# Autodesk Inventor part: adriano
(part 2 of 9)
sketch "スケッチ44"
  geometry: L1 (14.5, 50)-(14.5, 46) reference; L2 (0, 50)-(14.5, 50) reference; L3 (14.5, 46)-(0, 46) reference; L4 (1.7, 49.2)-(2.5, 49.2); L5 (2.5, 49.2)-(2.5, 46.8); L6 (2.5, 46.8)-(1.7, 46.8); L7 (1.7, 46.8)-(1.7, 49.2); L8 (3.3, 49.2)-(4.1, 49.2); L9 (4.1, 49.2)-(4.1, 46.8); L10 (4.1, 46.8)-(3.3, 46.8); L11 (3.3, 46.8)-(3.3, 49.2); L12 (6.5, 49.2)-(7.3, 49.2); L13 (7.3, 49.2)-(7.3, 46.8); L14 (7.3, 46.8)-(6.5, 46.8); L15 (6.5, 46.8)-(6.5, 49.2); L16 (8.1, 49.2)-(8.9, 49.2); L17 (8.9, 49.2)-(8.9, 46.8); L18 (8.9, 46.8)-(8.1, 46.8); L19 (8.1, 46.8)-(8.1, 49.2); L20 (9.7, 49.2)-(10.5, 49.2); L21 (10.5, 49.2)-(10.5, 46.8); L22 (10.5, 46.8)-(9.7, 46.8); L23 (9.7, 46.8)-(9.7, 49.2); L24 (11.3, 49.2)-(12.1, 49.2); L25 (12.1, 49.2)-(12.1, 46.8); L26 (12.1, 46.8)-(11.3, 46.8); L27 (11.3, 46.8)-(11.3, 49.2); L28 (12.9, 49.2)-(13.7, 49.2); L29 (13.7, 49.2)-(13.7, 46.8); L30 (13.7, 46.8)-(12.9, 46.8); L31 (12.9, 46.8)-(12.9, 49.2); L32 (4.9, 49.2)-(5.7, 49.2); L33 (5.7, 49.2)-(5.7, 46.8); L34 (5.7, 46.8)-(4.9, 46.8); L35 (4.9, 46.8)-(4.9, 49.2); L36 (0.1, 49.2)-(0.9, 49.2); L37 (0.9, 49.2)-(0.9, 46.8); L38 (0.9, 46.8)-(0.1, 46.8); L39 (0.1, 46.8)-(0.1, 49.2); 1 further point
  constraints: 72 end point, 18 parallel, 9 horizontal, 9 perpendicular
  dimensions: "d480" = 0.8 distance between parallel lines of L1 L29; "d481" = 0.8 distance of L28.start L28.end; "d482" = 0.8 distance between parallel lines of L31 L25; "d483" = 0.8 distance of L24.start L24.end; "d484" = 0.8 distance between parallel lines of L27 L21; "d485" = 0.8 distance of L20.start L20.end; "d486" = 0.8 distance between parallel lines of L23 L17; "d487" = 0.8 distance of L16.start L16.end; "d488" = 0.8 distance between parallel lines of L19 L13; "d489" = 0.8 distance of L12.start L12.end; "d490" = 0.8 distance between parallel lines of L15 L33; "d491" = 0.8 distance of L32.start L32.end; "d492" = 0.8 distance between parallel lines of L35 L9; "d493" = 0.8 distance of L8.start L8.end; "d494" = 0.8 distance between parallel lines of L11 L5; "d495" = 0.8 distance of L4.start L4.end; "d496" = 0.8 distance between parallel lines of L7 L37; "d497" = 0.8 distance of L36.start L36.end; "d498" = 0.8 distance between parallel lines of L2 L28; "d499" = 0.8 distance between parallel lines of L3 L30; "d500" = 0 distance between parallel lines of L30 L26; "d501" = 0 distance between parallel lines of L22 L26; "d502" = 0 distance between parallel lines of L18 L22; "d503" = 0 distance between parallel lines of L14 L18; "d504" = 0 distance between parallel lines of L34 L14; "d505" = 0 distance between parallel lines of L10 L34; "d506" = 0 distance between parallel lines of L10 L6; "d507" = 0 distance between parallel lines of L38 L6
extrude "押し出し43" cut sketch "スケッチ44" distance "d508" = 2; taper "d509" = 0 deg
sketch "スケッチ45"
  geometry: L1 (0, 50)-(43, 50) reference; L2 (0, 46)-(0, 50) reference; L3 (43, 46)-(0, 46) reference; L4 (0.8, 49.2)-(1.6, 49.2); L5 (1.6, 49.2)-(1.6, 46.8); L6 (1.6, 46.8)-(0.8, 46.8); L7 (0.8, 46.8)-(0.8, 49.2); L8 (2.4, 49.2)-(3.2, 49.2); L9 (3.2, 49.2)-(3.2, 46.8); L10 (3.2, 46.8)-(2.4, 46.8); L11 (2.4, 46.8)-(2.4, 49.2); L12 (4, 49.2)-(4.8, 49.2); L13 (4.8, 49.2)-(4.8, 46.8); L14 (4.8, 46.8)-(4, 46.8); L15 (4, 46.8)-(4, 49.2); L16 (5.6, 49.2)-(6.4, 49.2); L17 (6.4, 49.2)-(6.4, 46.8); L18 (6.4, 46.8)-(5.6, 46.8); L19 (5.6, 46.8)-(5.6, 49.2); L20 (7.2, 49.2)-(8, 49.2); L21 (8, 49.2)-(8, 46.8); L22 (8, 46.8)-(7.2, 46.8); L23 (7.2, 46.8)-(7.2, 49.2); L24 (8.8, 49.2)-(9.6, 49.2); L25 (9.6, 49.2)-(9.6, 46.8); L26 (9.6, 46.8)-(8.8, 46.8); L27 (8.8, 46.8)-(8.8, 49.2); L28 (12, 49.2)-(12.8, 49.2); L29 (12.8, 49.2)-(12.8, 46.8); L30 (12.8, 46.8)-(12, 46.8); L31 (12, 46.8)-(12, 49.2); L32 (13.6, 49.2)-(14.4, 49.2); L33 (14.4, 49.2)-(14.4, 46.8); L34 (14.4, 46.8)-(13.6, 46.8); L35 (13.6, 46.8)-(13.6, 49.2); L36 (15.2, 49.2)-(16, 49.2); L37 (16, 49.2)-(16, 46.8); L38 (16, 46.8)-(15.2, 46.8); L39 (15.2, 46.8)-(15.2, 49.2); L40 (16.8, 49.2)-(17.6, 49.2); L41 (17.6, 49.2)-(17.6, 46.8); L42 (17.6, 46.8)-(16.8, 46.8); L43 (16.8, 46.8)-(16.8, 49.2); L44 (18.4, 49.2)-(19.2, 49.2); L45 (19.2, 49.2)-(19.2, 46.8); L46 (19.2, 46.8)-(18.4, 46.8); L47 (18.4, 46.8)-(18.4, 49.2); L48 (20, 49.2)-(20.8, 49.2); L49 (20.8, 49.2)-(20.8, 46.8); L50 (20.8, 46.8)-(20, 46.8); L51 (20, 46.8)-(20, 49.2); L52 (21.6, 49.2)-(22.4, 49.2); L53 (22.4, 49.2)-(22.4, 46.8); L54 (22.4, 46.8)-(21.6, 46.8); L55 (21.6, 46.8)-(21.6, 49.2); L56 (23.2, 49.2)-(24, 49.2); L57 (24, 49.2)-(24, 46.8); L58 (24, 46.8)-(23.2, 46.8); L59 (23.2, 46.8)-(23.2, 49.2); L60 (24.8, 49.2)-(25.6, 49.2); L61 (25.6, 49.2)-(25.6, 46.8); L62 (25.6, 46.8)-(24.8, 46.8); L63 (24.8, 46.8)-(24.8, 49.2); L64 (26.4, 49.2)-(27.2, 49.2)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; 1 further point
  constraints: 216 end point, 54 parallel, 27 horizontal, 27 perpendicular
  dimensions: "d510" = 0.8 distance between parallel lines of L2 L7; "d511" = 0.8 distance of L4.start L4.end; "d512" = 0.8 distance between parallel lines of L11 L5; "d513" = 0.8 distance of L8.start L8.end; "d514" = 0.8 distance between parallel lines of L15 L9; "d515" = 0.8 distance of L12.start L12.end; "d516" = 0.8 distance between parallel lines of L19 L13; "d517" = 0.8 distance of L16.start L16.end; "d518" = 0.8 distance between parallel lines of L23 L17; "d519" = 0.8 distance of L20.start L20.end; "d520" = 0.8 distance between parallel lines of L27 L21; "d521" = 0.8 distance of L24.start L24.end; "d522" = 0.8 distance between parallel lines of L107 L25; "d523" = 0.8 distance of L104.start L104.end; "d524" = 0.8 distance between parallel lines of L31 L105; "d525" = 0.8 distance of L28.start L28.end; "d526" = 0.8 distance between parallel lines of L35 L29; "d527" = 0.8 distance of L32.start L32.end; "d528" = 0.8 distance between parallel lines of L39 L33; "d529" = 0.8 distance of L36.start L36.end; "d530" = 0.8 distance between parallel lines of L43 L37; "d531" = 0.8 distance of L40.start L40.end; "d532" = 0.8 distance between parallel lines of L47 L41; "d533" = 0.8 distance of L44.start L44.end; "d534" = 0.8 distance between parallel lines of L51 L45; "d535" = 0.8 distance of L48.start L48.end; "d536" = 0.8 distance between parallel lines of L55 L49; "d537" = 0.8 distance of L52.start L52.end; "d538" = 0.8 distance between parallel lines of L59 L53; "d539" = 0.8 distance of L56.start L56.end; "d540" = 0.8 distance between parallel lines of L63 L57; "d541" = 0.8 distance of L60.start L60.end; "d542" = 0.8 distance between parallel lines of L67 L61; "d543" = 0.8 distance of L64.start L64.end; "d544" = 0.8 distance between parallel lines of L71 L65; "d545" = 0.8 distance of L68.start L68.end; "d546" = 0.8 distance between parallel lines of L75 L69; "d547" = 0.8 distance of L72.start L72.end; "d548" = 0.8 distance between parallel lines of L79 L73; "d549" = 0.8 distance of L76.start L76.end; "d550" = 0.8 distance between parallel lines of L83 L77; "d551" = 0.8 distance of L80.start L80.end; "d552" = 0.8 distance between parallel lines of L87 L81; "d553" = 0.8 distance of L84.start L84.end; "d554" = 0.8 distance between parallel lines of L85 L91; "d555" = 0.8 distance of L88.start L88.end; "d556" = 0.8 distance between parallel lines of L95 L89; "d557" = 0.8 distance of L92.start L92.end; "d558" = 0.8 distance between parallel lines of L99 L93; "d559" = 0.8 distance of L96.start L96.end; "d560" = 0.8 distance between parallel lines of L103 L97; "d561" = 0.8 distance of L100.start L100.end; "d562" = 0.8 distance between parallel lines of L1 L4; "d563" = 0.8 distance between parallel lines of L3 L6; "d564" = 0 distance between parallel lines of L10 L6; "d565" = 0 distance between parallel lines of L14 L10; "d566" = 0 distance between parallel lines of L18 L14; "d567" = 0 distance between parallel lines of L22 L18; "d568" = 0 distance between parallel lines of L26 L22; "d569" = 0 distance between parallel lines of L106 L26; "d570" = 0 distance between parallel lines of L30 L106; "d571" = 0 distance between parallel lines of L34 L30; "d572" = 0 distance between parallel lines of L38 L34; "d573" = 0 distance between parallel lines of L42 L38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
extrude "押し出し44" cut sketch "スケッチ45" distance "d589" = 2; taper "d590" = 0 deg
sketch "スケッチ46"
  geometry: L1 (-0.5, 4)-(-0.5, 0) reference; L2 (-0.5, 0)-(0, 0) reference; L3 (-0.5, 4)-(0, 4); L4 (0, 4)-(0, 0); L5 (0, 0)-(-0.5, 0); L6 (-0.5, 0)-(-0.5, 4); 1 further point
  constraints: 8 end point, 2 parallel, 1 horizontal, 1 perpendicular
extrude "押し出し45" cut sketch "スケッチ46" distance "d592" = 0.5; taper "d593" = 0 deg
sketch "スケッチ47"
  geometry: L1 (40.8, 49.2)-(41.6, 49.2) reference; L2 (41.6, 49.2)-(41.6, 46.8) reference; L3 (41.6, 46.8)-(40.8, 46.8) reference; L4 (42.4, 49.2)-(43.2, 49.2); L5 (43.2, 49.2)-(43.2, 46.8); L6 (43.2, 46.8)-(42.4, 46.8); L7 (42.4, 46.8)-(42.4, 49.2); 1 further point
  constraints: 8 end point, 2 parallel, 1 horizontal, 1 perpendicular
  dimensions: "d596" = 0.8 distance of L4.start L4.end; "d598" = 0 distance between parallel lines of L3 L6; "d599" = 0 distance between parallel lines of L4 L1; "d600" = 0.8 distance between parallel lines of L7 L2
extrude "押し出し46" cut sketch "スケッチ47" distance "d601" = 0.5; taper "d602" = 0 deg
sketch "スケッチ48"
  geometry: L1 (11.588, -19.314)-(-20.412, -19.314) reference; L2 (11.588, -23.314)-(11.588, -19.314) reference; L3 (55.588, -23.314)-(11.588, -23.314) reference; L4 (11.588, -19.314)-(12.588, -19.314); L5 (12.588, -19.314)-(12.588, -23.314); L6 (12.588, -23.314)-(11.588, -23.314); L7 (11.588, -23.314)-(11.588, -19.314); 1 further point
  constraints: 8 end point, 2 parallel, 2 point on line, 1 horizontal, 1 perpendicular
  dimensions: "d603" = 1 distance of L4.start L4.end; "d605" = 0 distance between parallel lines of L4 L1
extrude "押し出し47" join sketch "スケッチ48" distance "d606" = 4; taper "d607" = 0 deg
sketch "スケッチ49"
  geometry: L1 (0, 50)-(4.5, 50) reference; L2 (0, 46)-(0, 50) reference; L3 (1, 49.2)-(1.8, 49.2); L4 (1.8, 49.2)-(1.8, 46.8); L5 (1.8, 46.8)-(1, 46.8); L6 (1, 46.8)-(1, 49.2); L7 (2.6, 49.2)-(3.4, 49.2); L8 (3.4, 49.2)-(3.4, 46.8); L9 (3.4, 46.8)-(2.6, 46.8); L10 (2.6, 46.8)-(2.6, 49.2); L11 (5.9, 46.8)-(5.1, 46.8) reference; 1 further point
  constraints: 16 end point, 4 parallel, 2 horizontal, 2 perpendicular
  dimensions: "d608" = 1 distance between parallel lines of L2 L6; "d609" = 0.8 distance between parallel lines of L10 L4; "d610" = 0.8 distance of L3.start L3.end; "d611" = 0.8 distance of L7.start L7.end; "d612" = 0.8 distance between parallel lines of L7 L1; "d613" = 0 distance from line of L7 L3.start; "d614" = 0 distance between parallel lines of L11 L9; "d615" = 0 distance between parallel lines of L5 L9
extrude "押し出し48" cut sketch "スケッチ49" distance "d616" = 2; taper "d617" = 0 deg
sketch "スケッチ50"
  geometry: L1 (0, 0)-(0, 26) reference; L2 (31.8, 0)-(0, 0) reference; L3 (4, 8)-(4, 0); L4 (9, 0)-(9, 8); L5 (15, 8)-(15, 2); L6 (15, 2)-(20, 2); L7 (20, 2)-(20, 8); A1 r 2.5 centre (6.5, 8) between (9, 8) and (4, 8); A2 r 2.5 centre (17.5, 8) between (20, 8) and (15, 8); 1 further point
  constraints: 10 end point, 4 point on circle, 4 tangent, 3 parallel, 2 centre point, 2 perpendicular, 2 point on line
  dimensions: "d618" = 6 distance between parallel lines of L5 L4; "d620" = 5 distance between parallel lines of L4 L3; "d621" = 5 distance of L5.end L6.end; "d622" = 4 distance between parallel lines of L1 L3; "d623" = 8 distance from line of L2 A1.centre; "d624" = 0 vertical distance of A1.centre A2.centre; "d625" = 2 distance between parallel lines of L2 L6
extrude "押し出し49" cut sketch "スケッチ50" distance "d626" = 8; taper "d627" = 0 deg
sketch "スケッチ51"
  geometry: L1 (9, -18)-(9, -26) reference; L2 (31.8, -26)-(9, -26) reference; L3 (4, -26)-(4, -18) reference; L4 (15, -18)-(15, -24); L5 (15, -24)-(20, -24); L6 (20, -24)-(20, -18); A1 r 2.5 centre (6.5, -18) between (9, -18) and (4, -18) reference; A2 r 2.5 centre (17.5, -18) between (20, -18) and (15, -18); 1 further point
  constraints: 6 end point, 2 parallel, 2 point on circle, 2 tangent, 1 centre point, 1 perpendicular
  dimensions: "d628" = 6 distance between parallel lines of L4 L1; "d629" = 5 distance of L4.end L5.end; "d630" = 2 distance between parallel lines of L2 L5; "d631" = 0 vertical distance of A1.centre A2.centre
extrude "押し出し50" cut sketch "スケッチ51" distance "d632" = 0.5; taper "d633" = 0 deg
sketch "スケッチ52"
  geometry: L1 (15, -24)-(15, -18) reference; L2 (20, -24)-(15, -24) reference; L3 (20, -18)-(20, -24) reference; L4 (15.6, -21.2)-(17.25, -21.2); L5 (17.25, -21.2)-(17.25, -23.4); L6 (17.25, -23.4)-(15.6, -23.4); L7 (15.6, -23.4)-(15.6, -21.2); L8 (17.75, -21.2)-(19.4, -21.2); L9 (19.4, -21.2)-(19.4, -23.4); L10 (19.4, -23.4)-(17.75, -23.4); L11 (17.75, -23.4)-(17.75, -21.2); L12 (15.6, -18.6)-(17.25, -18.6); L13 (17.25, -18.6)-(17.25, -20.6); L14 (17.25, -20.6)-(15.6, -20.6); L15 (15.6, -20.6)-(15.6, -18.6); L16 (17.75, -18.6)-(19.4, -18.6); L17 (19.4, -18.6)-(19.4, -20.6); L18 (19.4, -20.6)-(17.75, -20.6); L19 (17.75, -20.6)-(17.75, -18.6); L20 (15.6, -18)-(17.25, -18); L21 (17.25, -18)-(17.25, -16.35); L22 (17.75, -16.35)-(17.75, -18); L23 (17.75, -18)-(19.4, -18); A1 r 2.5 centre (17.5, -18) between (20, -18) and (15, -18) reference; A2 r 1.65 centre (17.25, -18) between (17.25, -16.35) and (15.6, -18); A3 r 1.65 centre (17.75, -18) between (19.4, -18) and (17.75, -16.35); 1 further point
  constraints: 40 end point, 9 parallel, 7 perpendicular, 4 horizontal, 4 point on circle, 2 centre point
  dimensions: "d634" = 0.25 distance from line of A1.centre L21; "d635" = 0.5 distance between parallel lines of L22 L21; "d636" = 0.5 distance between parallel lines of L19 L13; "d637" = 0.5 distance between parallel lines of L11 L5; "d638" = 0.25 distance from line of L13 A1.centre; "d639" = 0 distance between parallel lines of L5 L13; "d640" = 0.6 distance between parallel lines of L12 L20; "d641" = 0 distance between parallel lines of L16 L12; "d642" = 0 distance between parallel lines of L18 L14; "d643" = 0.6 distance between parallel lines of L14 L4; "d644" = 0 distance between parallel lines of L8 L4; "d645" = 0 distance between parallel lines of L10 L6; "d646" = 0.6 distance between parallel lines of L2 L6; "d647" = 0 distance between parallel lines of L20 L23; "d648" = 0 distance from line of A1.centre L23; "d649" = 0.6 distance between parallel lines of L15 L1; "d650" = 0.6 distance between parallel lines of L3 L17; "d651" = 0 distance between parallel lines of L7 L15; "d652" = 0 distance between parallel lines of L17 L9; "d653" = 0 horizontal distance of L12.start L20.start; "d654" = 0 vertical distance of L22.start L21.end; "d655" = 2 distance of L16.end L17.end
extrude "押し出し51" cut sketch "スケッチ52" distance "d656" = 4; taper "d657" = 0 deg
sketch "スケッチ53"
  geometry: L1 (-18.412, -5.686)-(13.588, -5.686); L2 (13.588, -5.686)-(13.588, -9.686); L3 (13.588, -9.686)-(-18.412, -9.686); L4 (-18.412, -9.686)-(-18.412, -5.686); 1 further point
  constraints: 8 end point, 2 parallel, 1 horizontal, 1 perpendicular
  dimensions: "d658" = 4 distance of L1.end L2.end; "d660" = 32 distance of L1.start L1.end
extrude "押し出し52" cut sketch "スケッチ53" distance "d661" = 36; taper "d662" = 0 deg
sketch "スケッチ54"
  geometry: L1 (-25.373, 26)-(-25.373, 30) reference; L2 (0, 26)-(-25.373, 26) reference; L3 (-25.373, 30)-(0, 30) reference; L4 (-24.573, 29.2)-(-23.773, 29.2); L5 (-23.773, 29.2)-(-23.773, 26.8); L6 (-23.773, 26.8)-(-24.573, 26.8); L7 (-24.573, 26.8)-(-24.573, 29.2); L8 (-22.973, 29.2)-(-22.173, 29.2); L9 (-22.173, 29.2)-(-22.173, 26.8); L10 (-22.173, 26.8)-(-22.973, 26.8); L11 (-22.973, 26.8)-(-22.973, 29.2); L12 (-21.373, 29.2)-(-20.573, 29.2); L13 (-20.573, 29.2)-(-20.573, 26.8); L14 (-20.573, 26.8)-(-21.373, 26.8); L15 (-21.373, 26.8)-(-21.373, 29.2); L16 (-19.773, 29.2)-(-18.973, 29.2); L17 (-18.973, 29.2)-(-18.973, 26.8); L18 (-18.973, 26.8)-(-19.773, 26.8); L19 (-19.773, 26.8)-(-19.773, 29.2); L20 (-18.173, 29.2)-(-17.373, 29.2); L21 (-17.373, 29.2)-(-17.373, 26.8); L22 (-17.373, 26.8)-(-18.173, 26.8); L23 (-18.173, 26.8)-(-18.173, 29.2); L24 (-16.573, 29.2)-(-15.773, 29.2); L25 (-15.773, 29.2)-(-15.773, 26.8); L26 (-15.773, 26.8)-(-16.573, 26.8); L27 (-16.573, 26.8)-(-16.573, 29.2); L28 (-13.373, 29.2)-(-12.573, 29.2); L29 (-12.573, 29.2)-(-12.573, 26.8); L30 (-12.573, 26.8)-(-13.373, 26.8); L31 (-13.373, 26.8)-(-13.373, 29.2); L32 (-11.773, 29.2)-(-10.973, 29.2); L33 (-10.973, 29.2)-(-10.973, 26.8); L34 (-10.973, 26.8)-(-11.773, 26.8); L35 (-11.773, 26.8)-(-11.773, 29.2); L36 (-10.173, 29.2)-(-9.373, 29.2); L37 (-9.373, 29.2)-(-9.373, 26.8); L38 (-9.373, 26.8)-(-10.173, 26.8); L39 (-10.173, 26.8)-(-10.173, 29.2); L40 (-8.573, 29.2)-(-7.773, 29.2); L41 (-7.773, 29.2)-(-7.773, 26.8); L42 (-7.773, 26.8)-(-8.573, 26.8); L43 (-8.573, 26.8)-(-8.573, 29.2); L44 (-6.973, 29.2)-(-6.173, 29.2); L45 (-6.173, 29.2)-(-6.173, 26.8); L46 (-6.173, 26.8)-(-6.973, 26.8); L47 (-6.973, 26.8)-(-6.973, 29.2); L48 (-5.373, 29.2)-(-4.573, 29.2); L49 (-4.573, 29.2)-(-4.573, 26.8); L50 (-4.573, 26.8)-(-5.373, 26.8); L51 (-5.373, 26.8)-(-5.373, 29.2); L52 (-2.173, 29.2)-(-1.373, 29.2); L53 (-1.373, 29.2)-(-1.373, 26.8); L54 (-1.373, 26.8)-(-2.173, 26.8); L55 (-2.173, 26.8)-(-2.173, 29.2); L56 (-14.973, 29.2)-(-14.173, 29.2); L57 (-14.173, 29.2)-(-14.173, 26.8); L58 (-14.173, 26.8)-(-14.973, 26.8); L59 (-14.973, 26.8)-(-14.973, 29.2); L60 (-3.773, 29.2)-(-2.973, 29.2); L61 (-2.973, 29.2)-(-2.973, 26.8); L62 (-2.973, 26.8)-(-3.773, 26.8); L63 (-3.773, 26.8)-(-3.773, 29.2); 1 further point
  constraints: 120 end point, 30 parallel, 15 horizontal, 15 perpendicular
  dimensions: "d663" = 0.8 distance between parallel lines of L1 L7; "d664" = 0.8 distance of L4.start L4.end; "d665" = 0.8 distance between parallel lines of L11 L5; "d666" = 0.8 distance of L8.start L8.end; "d667" = 0.8 distance between parallel lines of L15 L9; "d668" = 0.8 distance of L12.start L12.end; "d669" = 0.8 distance between parallel lines of L19 L13; "d670" = 0.8 distance of L16.start L16.end; "d671" = 0.8 distance between parallel lines of L23 L17; "d672" = 0.8 distance of L20.start L20.end; "d673" = 0.8 distance between parallel lines of L27 L21; "d674" = 0.8 distance of L24.start L24.end; "d675" = 0.8 distance between parallel lines of L59 L25; "d676" = 0.8 distance of L56.start L56.end; "d677" = 0.8 distance between parallel lines of L31 L57; "d678" = 0.8 distance of L28.start L28.end; "d679" = 0.8 distance between parallel lines of L35 L29; "d680" = 0.8 distance of L32.start L32.end; "d681" = 0.8 distance between parallel lines of L39 L33; "d682" = 0.8 distance of L36.start L36.end; "d683" = 0.8 distance between parallel lines of L43 L37; "d684" = 0.8 distance of L40.start L40.end; "d685" = 0.8 distance between parallel lines of L47 L41; "d686" = 0.8 distance of L44.start L44.end; "d687" = 0.8 distance between parallel lines of L51 L45; "d688" = 0.8 distance of L48.start L48.end; "d689" = 0.8 distance between parallel lines of L63 L49; "d690" = 0.8 distance of L60.start L60.end; "d691" = 0.8 distance between parallel lines of L55 L61; "d692" = 0.8 distance of L52.start L52.end; "d693" = 0.8 distance between parallel lines of L3 L4; "d694" = 0.8 distance between parallel lines of L2 L6; "d695" = 0 distance between parallel lines of L10 L6; "d696" = 0 distance between parallel lines of L14 L10; "d697" = 0 distance between parallel lines of L18 L14; "d698" = 0 distance between parallel lines of L22 L18; "d699" = 0 distance between parallel lines of L26 L22; "d700" = 0 distance between parallel lines of L58 L26; "d701" = 0 distance between parallel lines of L30 L58; "d702" = 0 distance between parallel lines of L34 L30; "d703" = 0 distance between parallel lines of L38 L34; "d704" = 0 distance between parallel lines of L42 L38; "d705" = 0 distance between parallel lines of L46 L42; "d706" = 0 distance between parallel lines of L50 L46; "d707" = 0 distance between parallel lines of L62 L50; "d708" = 0 distance between parallel lines of L54 L62
extrude "押し出し53" cut sketch "スケッチ54" distance "d709" = 2; taper "d710" = 0 deg
sketch "スケッチ55"
  geometry: L1 (-20.412, 10.686)-(12.588, 10.686); L2 (12.588, 10.686)-(12.588, -19.314); L3 (12.588, -19.314)-(-20.412, -19.314); L4 (-20.412, -19.314)-(-20.412, 10.686); 1 further point
  constraints: 8 end point, 2 parallel, 1 horizontal, 1 perpendicular
extrude "押し出し54" cut sketch "スケッチ55" distance "d711" = 2; taper "d712" = 0 deg
sketch "スケッチ56"
  geometry: L1 (12.588, 10.686)-(12.588, -19.314) reference; L2 (-20.412, 10.686)-(11.388, 10.686) reference; L3 (-20.412, -19.314)-(-20.412, 10.686) reference; L4 (11.588, -19.314)-(-20.412, -19.314) reference; L5 (-19.412, 9.686)-(12.588, 9.686); L6 (12.588, 9.686)-(12.588, -18.314); L7 (12.588, -18.314)-(-19.412, -18.314); L8 (-19.412, -18.314)-(-19.412, 9.686); 1 further point
  constraints: 8 end point, 2 parallel, 1 horizontal, 1 perpendicular, 1 point on line
  dimensions: "d713" = 1 distance between parallel lines of L2 L5; "d714" = 1 distance between parallel lines of L8 L3; "d715" = 1 distance between parallel lines of L4 L7
extrude "押し出し55" cut sketch "スケッチ56" distance "d716" = 4; taper "d717" = 0 deg
sketch "スケッチ57"
  geometry: L1 (-20.412, 10.686)-(11.388, 10.686) reference; L2 (12.588, 9.686)-(0.588, 9.686); L3 (0.588, 9.686)-(0.588, 10.686); L4 (0.588, 10.686)-(12.588, 10.686); L5 (12.588, 10.686)-(12.588, 9.686); 1 further point
  constraints: 8 end point, 2 parallel, 1 horizontal, 1 perpendicular, 1 point on line
  dimensions: "d718" = 12 distance of L3.end L4.end
extrude "押し出し56" join sketch "スケッチ57" distance "d720" = 2; taper "d721" = 0 deg
fillet "フィレット1" dims "d723" = 2
fillet "フィレット2" dims "d724" = 2
sketch "スケッチ58"
  geometry: L1 (12.588, 9.686)-(12.588, -18.314) reference; L2 (-19.412, 9.686)-(12.588, 9.686) reference; L3 (12.588, -18.314)-(-19.412, -18.314) reference; L4 (6.588, -2.314)-(12.588, -2.314); L5 (12.588, -2.314)-(12.588, -8.314); L6 (12.588, -8.314)-(6.588, -8.314); L7 (6.588, -8.314)-(6.588, -2.314); 1 further point
  constraints: 8 end point, 2 parallel, 1 horizontal, 1 perpendicular, 1 point on line
  dimensions: "d725" = 6 distance of L4.start L4.end; "d727" = 12 distance between parallel lines of L2 L4; "d728" = 10 distance between parallel lines of L3 L6
extrude "押し出し57" join sketch "スケッチ58" distance "d729" = 1; taper "d730" = 0 deg
sketch "スケッチ59"
  geometry: L1 (12.588, -2.314)-(12.588, -8.314) reference; L2 (12.588, -2.314)-(6.588, -2.314) reference; L3 (6.588, -2.314)-(6.588, -8.314) reference; L4 (12.588, -8.314)-(7.588, -8.314); L5 (7.588, -8.314)-(7.588, -2.314); L6 (7.588, -2.314)-(12.588, -2.314); L7 (12.588, -2.314)-(12.588, -8.314); 1 further point
  constraints: 8 end point, 2 parallel, 1 horizontal, 1 perpendicular, 1 point on line
  dimensions: "d731" = 1 distance between parallel lines of L5 L3
extrude "押し出し58" join sketch "スケッチ59" distance "d732" = 1; taper "d733" = 0 deg
sketch "スケッチ60"
  geometry: L1 (12.588, -2.314)-(12.588, -8.314) reference; L2 (12.588, -2.314)-(7.588, -2.314) reference; L3 (7.588, -2.314)-(7.588, -8.314) reference; L4 (12.588, -8.314)-(8.588, -8.314); L5 (8.588, -8.314)-(8.588, -2.314); L6 (8.588, -2.314)-(12.588, -2.314); L7 (12.588, -2.314)-(12.588, -8.314); 1 further point
  constraints: 8 end point, 2 parallel, 1 horizontal, 1 perpendicular, 1 point on line
  dimensions: "d734" = 1 distance between parallel lines of L5 L3
extrude "押し出し59" join sketch "スケッチ60" distance "d735" = 1; taper "d736" = 0 deg
sketch "スケッチ61"
  geometry: L1 (12.588, -2.314)-(12.588, -8.314) reference; L2 (12.588, -2.314)-(8.588, -2.314) reference; L3 (8.588, -2.314)-(8.588, -8.314) reference; L4 (12.588, -8.314)-(9.588, -8.314); L5 (9.588, -8.314)-(9.588, -2.314); L6 (9.588, -2.314)-(12.588, -2.314); L7 (12.588, -2.314)-(12.588, -8.314); 1 further point
  constraints: 8 end point, 2 parallel, 1 horizontal, 1 perpendicular, 1 point on line
  dimensions: "d737" = 1 distance between parallel lines of L5 L3
extrude "押し出し60" join sketch "スケッチ61" distance "d738" = 1; taper "d739" = 0 deg
sketch "スケッチ62"
  geometry: L1 (12.588, -2.314)-(12.588, -8.314) reference; L2 (12.588, -2.314)-(9.588, -2.314) reference; L3 (9.588, -2.314)-(9.588, -8.314) reference; L4 (12.588, -8.314)-(10.588, -8.314); L5 (10.588, -8.314)-(10.588, -2.314); L6 (10.588, -2.314)-(12.588, -2.314); L7 (12.588, -2.314)-(12.588, -8.314); 1 further point
  constraints: 8 end point, 2 parallel, 1 horizontal, 1 perpendicular, 1 point on line
  dimensions: "d740" = 1 distance between parallel lines of L3 L5
extrude "押し出し61" join sketch "スケッチ62" distance "d741" = 1; taper "d742" = 0 deg
sketch "スケッチ63"
  geometry: L1 (0, 0)-(0, 5) reference; L2 (0, 0)-(0, 4); L3 (0, 4)-(5, 0); L4 (5, 0)-(0, 0); 1 further point
  constraints: 6 end point, 1 collinear, 1 perpendicular
  dimensions: "d743" = 4 distance of L1.start L2.end; "d744" = 5 distance of L3.end L1.start
extrude "押し出し62" join sketch "スケッチ63" distance "d745" = 12; taper "d746" = 0 deg
sketch "スケッチ64"
  geometry: L1 (6, 5)-(6, 0) reference; L2 (0, 0)-(0, 1) reference; L3 (6, 0)-(1, 0); L4 (1, 0)-(6, 4); L5 (6, 4)-(6, 0); 1 further point
  constraints: 6 end point, 1 collinear, 1 perpendicular
  dimensions: "d747" = 4 distance of L4.end L1.end; "d748" = 5 distance of L1.end L3.end
extrude "押し出し63" join sketch "スケッチ64" distance "d749" = 10; taper "d750" = 0 deg
sketch "スケッチ65"
  geometry: L1 (54.588, 40.686)-(54.588, 32.686) reference; L2 (87.588, 32.686)-(54.588, 32.686) reference; L3 (87.588, 32.686)-(87.588, 40.686) reference; L4 (87.588, 40.686)-(54.588, 40.686) reference; L5 (55.588, 40.686)-(86.588, 40.686); L6 (86.588, 40.686)-(86.588, 32.686); L7 (86.588, 32.686)-(55.588, 32.686); L8 (55.588, 32.686)-(55.588, 40.686); 1 further point
  constraints: 8 end point, 2 parallel, 2 point on line, 1 horizontal, 1 perpendicular
  dimensions: "d751" = 1 distance between parallel lines of L8 L1; "d752" = 1 distance between parallel lines of L3 L6
extrude "押し出し64" join sketch "スケッチ65" distance "d753" = 1; taper "d754" = 0 deg
sketch "スケッチ66"
  geometry: L1 (-17, 18)-(-17, 17) reference; L2 (-48, 17)-(-48, 18) reference; L3 (-48, 18)-(-17, 18) reference; L4 (-25, 18)-(-40, 18); L5 (-40, 18)-(-40, 31); L6 (-40, 31)-(-25, 31); L7 (-25, 31)-(-25, 18); L8 (-75.5, 30)-(13.717, 30) reference; 1 further point
  constraints: 8 end point, 2 parallel, 1 horizontal, 1 perpendicular, 1 point on line
  dimensions: "d755" = 8 distance between parallel lines of L5 L2; "d756" = 8 distance between parallel lines of L7 L1; "d757" = 1 distance between parallel lines of L8 L6
extrude "押し出し65" cut sketch "スケッチ66" distance "d758" = 12; taper "d759" = 0 deg
sketch "スケッチ67"
  geometry: L1 (63.588, 32.686)-(78.588, 32.686); L2 (78.588, 32.686)-(78.588, 20.686); L3 (78.588, 20.686)-(63.588, 20.686); L4 (63.588, 20.686)-(63.588, 32.686); 1 further point
  constraints: 8 end point, 2 parallel, 1 horizontal, 1 perpendicular
extrude "step_00" join sketch "スケッチ67" distance "d760" = 1; taper "d761" = 0 deg
sketch "スケッチ68"
  geometry: L1 (63.588, 20.686)-(63.588, 32.686) reference; L2 (78.588, 32.686)-(63.588, 32.686) reference; L3 (78.588, 20.686)-(63.588, 20.686); L4 (63.588, 20.686)-(63.588, 31.686); L5 (63.588, 31.686)-(78.588, 31.686); L6 (78.588, 31.686)-(78.588, 20.686); 1 further point
  constraints: 8 end point, 2 parallel, 1 horizontal, 1 perpendicular, 1 point on line
  dimensions: "d762" = 1 distance between parallel lines of L5 L2
extrude "押し出し67" join sketch "スケッチ68" distance "d763" = 1; taper "d764" = 0 deg
sketch "スケッチ69"
  geometry: L1 (63.588, 20.686)-(63.588, 31.686) reference; L2 (78.588, 20.686)-(63.588, 20.686) reference; L3 (78.588, 31.686)-(78.588, 20.686) reference; L4 (78.588, 31.686)-(63.588, 31.686) reference; 1 further point
sketch "スケッチ70"
  geometry: L1 (63.588, 20.686)-(63.588, 31.686) reference; L2 (78.588, 31.686)-(63.588, 31.686) reference; L3 (78.588, 20.686)-(63.588, 20.686); L4 (63.588, 20.686)-(63.588, 30.686); L5 (63.588, 30.686)-(78.588, 30.686); L6 (78.588, 30.686)-(78.588, 20.686); 1 further point
  constraints: 8 end point, 2 parallel, 1 horizontal, 1 perpendicular, 1 point on line
  dimensions: "d765" = 1 distance between parallel lines of L5 L2
extrude "押し出し68" join sketch "スケッチ70" distance "d766" = 1; taper "d767" = 0 deg
sketch "スケッチ71"
  geometry: L1 (63.588, 20.686)-(63.588, 30.686) reference; L2 (78.588, 30.686)-(63.588, 30.686) reference; L3 (78.588, 20.686)-(63.588, 20.686); L4 (63.588, 20.686)-(63.588, 29.686); L5 (63.588, 29.686)-(78.588, 29.686); L6 (78.588, 29.686)-(78.588, 20.686); 1 further point
  constraints: 8 end point, 2 parallel, 1 horizontal, 1 perpendicular, 1 point on line
  dimensions: "d768" = 1 distance between parallel lines of L2 L5
extrude "押し出し69" join sketch "スケッチ71" distance "d769" = 1; taper "d770" = 0 deg
sketch "スケッチ72"
  geometry: L1 (78.588, 29.686)-(78.588, 20.686) reference; L2 (78.588, 29.686)-(63.588, 29.686) reference; L3 (63.588, 20.686)-(78.588, 20.686); L4 (78.588, 20.686)-(78.588, 28.686); L5 (78.588, 28.686)-(63.588, 28.686); L6 (63.588, 28.686)-(63.588, 20.686); 1 further point
  constraints: 8 end point, 2 parallel, 1 horizontal, 1 perpendicular, 1 point on line
  dimensions: "d771" = 1 distance between parallel lines of L5 L2
extrude "押し出し70" join sketch "スケッチ72" distance "d772" = 1; taper "d773" = 0 deg
sketch "スケッチ73"
  geometry: L1 (78.588, 20.686)-(63.588, 20.686) reference; L2 (78.588, 28.686)-(78.588, 20.686) reference; L3 (78.588, 28.686)-(63.588, 28.686) reference; L4 (63.588, 20.686)-(78.588, 20.686); L5 (78.588, 20.686)-(78.588, 27.686); L6 (78.588, 27.686)-(63.588, 27.686); L7 (63.588, 27.686)-(63.588, 20.686); 1 further point
  constraints: 8 end point, 2 parallel, 1 horizontal, 1 perpendicular, 1 point on line
  dimensions: "d774" = 1 distance between parallel lines of L3 L6
extrude "押し出し71" join sketch "スケッチ73" distance "d775" = 1; taper "d776" = 0 deg
sketch "スケッチ74"
  geometry: L1 (78.588, 20.686)-(63.588, 20.686) reference; L2 (78.588, 27.686)-(78.588, 20.686) reference; L3 (78.588, 27.686)-(63.588, 27.686) reference; L4 (63.588, 20.686)-(78.588, 20.686); L5 (78.588, 20.686)-(78.588, 26.686); L6 (78.588, 26.686)-(63.588, 26.686); L7 (63.588, 26.686)-(63.588, 20.686); 1 further point
  constraints: 8 end point, 2 parallel, 1 horizontal, 1 perpendicular, 1 point on line
  dimensions: "d777" = 1 distance between parallel lines of L3 L6
extrude "押し出し72" join sketch "スケッチ74" distance "d778" = 1; taper "d779" = 0 deg
sketch "スケッチ75"
  geometry: L1 (78.588, 20.686)-(63.588, 20.686) reference; L2 (78.588, 26.686)-(78.588, 20.686) reference; L3 (78.588, 26.686)-(63.588, 26.686) reference; L4 (63.588, 20.686)-(78.588, 20.686); L5 (78.588, 20.686)-(78.588, 25.686); L6 (78.588, 25.686)-(63.588, 25.686); L7 (63.588, 25.686)-(63.588, 20.686); 1 further point
  constraints: 8 end point, 2 parallel, 1 horizontal, 1 perpendicular, 1 point on line
  dimensions: "d780" = 1 distance between parallel lines of L6 L3
extrude "step_end" join sketch "スケッチ75" distance "d781" = 1; taper "d782" = 0 deg
sketch "スケッチ76"
  geometry: L1 (-54, 26)-(-89.5, 26) reference; L2 (-54, 30)-(-58, 30); L3 (-58, 30)-(-58, 26); L4 (-58, 26)-(-54, 26); L5 (-54, 26)-(-54, 30); L6 (-62, 17)-(-62, 18) reference; 1 further point
  constraints: 8 end point, 2 parallel, 1 horizontal, 1 perpendicular, 1 point on line
  dimensions: "d783" = 4 distance between parallel lines of L6 L3
extrude "押し出し74" cut sketch "スケッチ76" distance "d784" = 2; taper "d785" = 0 deg
sketch "スケッチ77"
  geometry: L1 (-39, 30)-(-39, 26) reference; L2 (-0.283, 26)-(-39, 26) reference; L3 (-39, 30)-(-35, 30); L4 (-35, 30)-(-35, 26); L5 (-35, 26)-(-39, 26); L6 (-39, 26)-(-39, 30); L7 (-31, 17)-(-31, 18) reference; 1 further point
  constraints: 8 end point, 2 parallel, 1 horizontal, 1 perpendicular, 1 point on line
  dimensions: "d786" = 4 distance between parallel lines of L7 L4
extrude "押し出し75" cut sketch "スケッチ77" distance "d787" = 2; taper "d788" = 0 deg
sketch "スケッチ78"
  geometry: L1 (-89.5, 30)-(-58, 30) reference; L2 (-89.5, 26)-(-89.5, 30) reference; L3 (-58, 26)-(-89.5, 26) reference; L4 (-88.7, 29.2)-(-87.9, 29.2); L5 (-87.9, 29.2)-(-87.9, 26.8); L6 (-87.9, 26.8)-(-88.7, 26.8); L7 (-88.7, 26.8)-(-88.7, 29.2); L8 (-87.1, 29.2)-(-86.3, 29.2); L9 (-86.3, 29.2)-(-86.3, 26.749); L10 (-86.3, 26.749)-(-87.1, 26.749); L11 (-87.1, 26.749)-(-87.1, 29.2); L12 (-85.5, 29.2)-(-84.7, 29.2); L13 (-84.7, 29.2)-(-84.7, 26.749); L14 (-84.7, 26.749)-(-85.5, 26.749); L15 (-85.5, 26.749)-(-85.5, 29.2); L16 (-82.3, 29.2)-(-81.5, 29.2); L17 (-81.5, 29.2)-(-81.5, 26.749); L18 (-81.5, 26.749)-(-82.3, 26.749); L19 (-82.3, 26.749)-(-82.3, 29.2); L20 (-80.7, 29.2)-(-79.9, 29.2); L21 (-79.9, 29.2)-(-79.9, 26.749); L22 (-79.9, 26.749)-(-80.7, 26.749); L23 (-80.7, 26.749)-(-80.7, 29.2); L24 (-79.1, 29.2)-(-78.3, 29.2); L25 (-78.3, 29.2)-(-78.3, 26.749); L26 (-78.3, 26.749)-(-79.1, 26.749); L27 (-79.1, 26.749)-(-79.1, 29.2); L28 (-77.5, 29.2)-(-76.7, 29.2); L29 (-76.7, 29.2)-(-76.7, 26.749); L30 (-76.7, 26.749)-(-77.5, 26.749); L31 (-77.5, 26.749)-(-77.5, 29.2); L32 (-74.3, 29.2)-(-73.5, 29.2); L33 (-73.5, 29.2)-(-73.5, 26.749); L34 (-73.5, 26.749)-(-74.3, 26.749); L35 (-74.3, 26.749)-(-74.3, 29.2); L36 (-72.7, 29.2)-(-71.9, 29.2); L37 (-71.9, 29.2)-(-71.9, 26.749); L38 (-71.9, 26.749)-(-72.7, 26.749); L39 (-72.7, 26.749)-(-72.7, 29.2); L40 (-71.1, 29.2)-(-70.3, 29.2); L41 (-70.3, 29.2)-(-70.3, 26.749); L42 (-70.3, 26.749)-(-71.1, 26.749); L43 (-71.1, 26.749)-(-71.1, 29.2); L44 (-69.5, 29.2)-(-68.7, 29.2); L45 (-68.7, 29.2)-(-68.7, 26.749); L46 (-68.7, 26.749)-(-69.5, 26.749); L47 (-69.5, 26.749)-(-69.5, 29.2); L48 (-67.9, 29.2)-(-67.1, 29.2); L49 (-67.1, 29.2)-(-67.1, 26.749); L50 (-67.1, 26.749)-(-67.9, 26.749); L51 (-67.9, 26.749)-(-67.9, 29.2); L52 (-66.3, 29.2)-(-65.5, 29.2); L53 (-65.5, 29.2)-(-65.5, 26.749); L54 (-65.5, 26.749)-(-66.3, 26.749); L55 (-66.3, 26.749)-(-66.3, 29.2); L56 (-64.7, 29.2)-(-63.9, 29.2); L57 (-63.9, 29.2)-(-63.9, 26.749); L58 (-63.9, 26.749)-(-64.7, 26.749); L59 (-64.7, 26.749)-(-64.7, 29.2); L60 (-63.1, 29.2)-(-62.3, 29.2); L61 (-62.3, 29.2)-(-62.3, 26.749); L62 (-62.3, 26.749)-(-63.1, 26.749); L63 (-63.1, 26.749)-(-63.1, 29.2); L64 (-83.9, 29.2)-(-83.1, 29.2)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; 1 further point
  constraints: 136 end point, 34 parallel, 17 horizontal, 17 perpendicular
  dimensions: "d789" = 0.8 distance between parallel lines of L2 L7; "d790" = 0.8 distance of L4.start L4.end; "d791" = 0.8 distance between parallel lines of L11 L5; "d792" = 0.8 distance of L8.start L8.end; "d793" = 0.8 distance between parallel lines of L15 L9; "d794" = 0.8 distance of L12.start L12.end; "d795" = 0.8 distance between parallel lines of L13 L67; "d796" = 0.8 distance of L64.start L64.end; "d797" = 0.8 distance between parallel lines of L19 L65; "d798" = 0.8 distance of L16.start L16.end; "d799" = 0.8 distance between parallel lines of L23 L17; "d800" = 0.8 distance of L20.start L20.end; "d801" = 0.8 distance between parallel lines of L27 L21; "d802" = 0.8 distance of L24.start L24.end; "d803" = 0.8 distance between parallel lines of L31 L25; "d804" = 0.8 distance of L28.start L28.end; "d805" = 0.8 distance between parallel lines of L71 L29; "d806" = 0.8 distance of L68.start L68.end; "d807" = 0.8 distance between parallel lines of L35 L69; "d808" = 0.8 distance of L32.start L32.end; "d809" = 0.8 distance between parallel lines of L39 L33; "d810" = 0.8 distance of L36.start L36.end; "d811" = 0.8 distance between parallel lines of L43 L37; "d812" = 0.8 distance of L40.start L40.end; "d813" = 0.8 distance between parallel lines of L47 L41; "d814" = 0.8 distance of L44.start L44.end; "d815" = 0.8 distance between parallel lines of L51 L45; "d816" = 0.8 distance of L48.start L48.end; "d817" = 0.8 distance between parallel lines of L55 L49; "d818" = 0.8 distance of L52.start L52.end; "d819" = 0.8 distance between parallel lines of L59 L53; "d820" = 0.8 distance of L56.start L56.end; "d821" = 0.8 distance between parallel lines of L63 L57; "d822" = 0.8 distance of L60.start L60.end; "d823" = 0.8 distance between parallel lines of L4 L1; "d824" = 0.8 distance between parallel lines of L3 L6
extrude "押し出し76" cut sketch "スケッチ78" distance "d825" = 2; taper "d826" = 0 deg
sketch "スケッチ79"
  geometry: L1 (-0.283, 26)-(-35, 26) reference; L2 (-0.283, 26)-(-0.283, 30) reference; L3 (-35, 30)-(-0.283, 30) reference; L4 (-1.083, 29.2)-(-1.883, 29.2); L5 (-1.883, 29.2)-(-1.883, 26.8); L6 (-1.883, 26.8)-(-1.083, 26.8); L7 (-1.083, 26.8)-(-1.083, 29.2); L8 (-2.683, 29.2)-(-3.483, 29.2); L9 (-3.483, 29.2)-(-3.483, 26.8); L10 (-3.483, 26.8)-(-2.683, 26.8); L11 (-2.683, 26.8)-(-2.683, 29.2); L12 (-5.883, 29.2)-(-6.683, 29.2); L13 (-6.683, 29.2)-(-6.683, 26.8); L14 (-6.683, 26.8)-(-5.883, 26.8); L15 (-5.883, 26.8)-(-5.883, 29.2); L16 (-7.483, 29.2)-(-8.283, 29.2); L17 (-8.283, 29.2)-(-8.283, 26.8); L18 (-8.283, 26.8)-(-7.483, 26.8); L19 (-7.483, 26.8)-(-7.483, 29.2); L20 (-9.083, 29.2)-(-9.883, 29.2); L21 (-9.883, 29.2)-(-9.883, 26.8); L22 (-9.883, 26.8)-(-9.083, 26.8); L23 (-9.083, 26.8)-(-9.083, 29.2); L24 (-10.683, 29.2)-(-11.483, 29.2); L25 (-11.483, 29.2)-(-11.483, 26.8); L26 (-11.483, 26.8)-(-10.683, 26.8); L27 (-10.683, 26.8)-(-10.683, 29.2); L28 (-12.283, 29.2)-(-13.083, 29.2); L29 (-13.083, 29.2)-(-13.083, 26.8); L30 (-13.083, 26.8)-(-12.283, 26.8); L31 (-12.283, 26.8)-(-12.283, 29.2); L32 (-13.883, 29.2)-(-14.683, 29.2); L33 (-14.683, 29.2)-(-14.683, 26.8); L34 (-14.683, 26.8)-(-13.883, 26.8); L35 (-13.883, 26.8)-(-13.883, 29.2); L36 (-15.483, 29.2)-(-16.283, 29.2); L37 (-16.283, 29.2)-(-16.283, 26.8); L38 (-16.283, 26.8)-(-15.483, 26.8); L39 (-15.483, 26.8)-(-15.483, 29.2); L40 (-18.683, 29.2)-(-19.483, 29.2); L41 (-19.483, 29.2)-(-19.483, 26.8); L42 (-19.483, 26.8)-(-18.683, 26.8); L43 (-18.683, 26.8)-(-18.683, 29.2); L44 (-20.283, 29.2)-(-21.083, 29.2); L45 (-21.083, 29.2)-(-21.083, 26.8); L46 (-21.083, 26.8)-(-20.283, 26.8); L47 (-20.283, 26.8)-(-20.283, 29.2); L48 (-21.883, 29.2)-(-22.683, 29.2); L49 (-22.683, 29.2)-(-22.683, 26.8); L50 (-22.683, 26.8)-(-21.883, 26.8); L51 (-21.883, 26.8)-(-21.883, 29.2); L52 (-23.483, 29.2)-(-24.283, 29.2); L53 (-24.283, 29.2)-(-24.283, 26.8); L54 (-24.283, 26.8)-(-23.483, 26.8); L55 (-23.483, 26.8)-(-23.483, 29.2); L56 (-25.083, 29.2)-(-25.883, 29.2); L57 (-25.883, 29.2)-(-25.883, 26.8); L58 (-25.883, 26.8)-(-25.083, 26.8); L59 (-25.083, 26.8)-(-25.083, 29.2); L60 (-26.683, 29.2)-(-27.483, 29.2); L61 (-27.483, 29.2)-(-27.483, 26.8); L62 (-27.483, 26.8)-(-26.683, 26.8); L63 (-26.683, 26.8)-(-26.683, 29.2); L64 (-29.883, 29.2)-(-30.683, 29.2)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; 1 further point
  constraints: 152 end point, 38 parallel, 19 horizontal, 19 perpendicular
  dimensions: "d827" = 0.8 distance between parallel lines of L2 L7; "d828" = 0.8 distance between parallel lines of L11 L5; "d829" = 0.8 distance of L4.start L4.end; "d830" = 0.8 distance of L8.start L8.end; "d831" = 0.8 distance between parallel lines of L9 L69; "d832" = 0.8 distance of L68.start L68.end; "d833" = 0.8 distance between parallel lines of L15 L71; "d834" = 0.8 distance of L12.start L12.end; "d835" = 0.8 distance between parallel lines of L19 L13; "d836" = 0.8 distance of L16.start L16.end; "d837" = 0.8 distance between parallel lines of L17 L23; "d838" = 0.8 distance of L20.start L20.end; "d839" = 0.8 distance between parallel lines of L21 L27; "d840" = 0.8 distance of L24.start L24.end; "d841" = 0.8 distance between parallel lines of L25 L31; "d842" = 0.8 distance of L28.start L28.end; "d843" = 0.8 distance between parallel lines of L29 L35; "d844" = 0.8 distance of L32.start L32.end; "d845" = 0.8 distance between parallel lines of L33 L39; "d846" = 0.8 distance of L36.start L36.end; "d847" = 0.8 distance between parallel lines of L37 L73; "d848" = 0.8 distance of L72.start L72.end; "d849" = 0.8 distance between parallel lines of L43 L75; "d850" = 0.8 distance of L40.start L40.end; "d851" = 0.8 distance between parallel lines of L47 L41; "d852" = 0.8 distance of L44.start L44.end; "d853" = 0.8 distance between parallel lines of L45 L51; "d854" = 0.8 distance of L48.start L48.end; "d855" = 0.8 distance between parallel lines of L49 L55; "d856" = 0.8 distance of L52.start L52.end; "d857" = 0.8 distance between parallel lines of L53 L59; "d858" = 0.8 distance of L56.start L56.end; "d859" = 0.8 distance between parallel lines of L57 L63; "d860" = 0.8 distance of L60.start L60.end; "d861" = 0.8 distance between parallel lines of L77 L61; "d862" = 0.8 distance of L76.start L76.end; "d863" = 0.8 distance between parallel lines of L67 L79; "d864" = 0.8 distance of L64.start L64.end; "d865" = 0.8 distance between parallel lines of L3 L4; "d866" = 0.8 distance between parallel lines of L1 L6; "d867" = 0 distance between parallel lines of L10 L6; "d868" = 0 distance between parallel lines of L70 L10; "d869" = 0 distance between parallel lines of L14 L70; "d870" = 0 distance between parallel lines of L18 L14; "d871" = 0 distance between parallel lines of L22 L18; "d872" = 0 distance between parallel lines of L80 L26; "d873" = 0 distance between parallel lines of L30 L26; "d874" = 0 distance between parallel lines of L34 L30; "d875" = 0 distance between parallel lines of L38 L34; "d876" = 0 distance between parallel lines of L74 L38; "d877" = 0 distance between parallel lines of L42 L74; "d878" = 0 distance between parallel lines of L46 L42; "d879" = 0 distance between parallel lines of L50 L46; "d880" = 0 distance between parallel lines of L54 L50; "d881" = 0.8 distance between parallel lines of L1 L58; "d882" = 0 distance between parallel lines of L62 L58; "d883" = 0 distance between parallel lines of L78 L62; "d884" = 0 distance between parallel lines of L66 L78
extrude "押し出し77" cut sketch "スケッチ79" distance "d885" = 2; taper "d886" = 0 deg
sketch "スケッチ80"
  geometry: L1 (86.588, 32.686)-(86.588, 40.686) reference; L2 (86.588, 40.686)-(55.588, 40.686) reference; L3 (55.588, 40.686)-(55.588, 32.686) reference; L4 (59.588, 40.686)-(60.588, 40.686); L5 (60.588, 40.686)-(60.588, 25.686); L6 (60.588, 25.686)-(59.588, 25.686); L7 (59.588, 25.686)-(59.588, 40.686); L8 (81.588, 40.686)-(82.588, 40.686); L9 (82.588, 40.686)-(82.588, 25.686); L10 (82.588, 25.686)-(81.588, 25.686); L11 (81.588, 25.686)-(81.588, 40.686); 1 further point
  constraints: 16 end point, 4 parallel, 2 horizontal, 2 perpendicular, 2 point on line
  dimensions: "d887" = 4 distance between parallel lines of L7 L3; "d888" = 1 distance between parallel lines of L5 L7; "d889" = 4 distance between parallel lines of L1 L9; "d890" = 1 distance between parallel lines of L9 L11; "d891" = 15 distance of L6.end L4.start; "d892" = 15 distance of L8.end L9.end
extrude "押し出し78" join sketch "スケッチ80" distance "d893" = 24; taper "d894" = 0 deg
sketch "スケッチ82"
  geometry: L1 (38, 38)-(59, 38); L2 (59, 38)-(59, 62); L3 (59, 62)-(38, 62); L4 (38, 62)-(38, 38); 1 further point
  constraints: 8 end point, 2 parallel, 1 horizontal, 1 perpendicular
extrude "押し出し79" join sketch "スケッチ82" distance "d898" = 1.5; taper "d899" = 0 deg
sketch "スケッチ83"
  geometry: L1 (37, 62)-(60, 62); L2 (60, 62)-(60, 38); L3 (60, 38)-(37, 38); L4 (37, 38)-(37, 62); 1 further point
  constraints: 8 end point, 2 parallel, 1 horizontal, 1 perpendicular
extrude "押し出し80" cut sketch "スケッチ83" distance "d900" = 0.5; taper "d901" = 0 deg
sketch "スケッチ84"
  geometry: L1 (14.5, -8)-(14.5, 16) reference; L2 (0, 16)-(14.5, 16) reference; L3 (0, 0)-(0, 16) reference; L4 (14.5, -8)-(7, -8) reference; L5 (0, 16)-(14.5, 16); L6 (14.5, 16)-(14.5, 10.722); L7 (14.5, 10.722)-(0, 16); 1 further point
  constraints: 6 end point, 1 parallel, 1 perpendicular
  dimensions: "d902" = 0 distance from line of L3 L5.start; "d903" = 0 distance between parallel lines of L6 L1; "d904" = 20 deg angle of L7 L2; "d937" = 0 distance between parallel lines of L2 L5
extrude "押し出し81" cut sketch "スケッチ84" distance "d905" = 30; taper "d906" = 0 deg
sketch "スケッチ85"
  geometry: L1 (0, 0)-(0, 8) reference; L2 (7.5, 0)-(0, 0) reference; L3 (7.5, 0)-(7.5, 18.722) reference; L4 (1, 10)-(1, 0); L5 (6.5, 0)-(6.5, 10); A1 r 2.75 centre (3.75, 10) between (6.5, 10) and (1, 10); 1 further point
  constraints: 4 end point, 2 point on circle, 2 point on line, 2 tangent, 1 centre point, 1 parallel, 1 perpendicular
  dimensions: "d907" = 1 distance between parallel lines of L4 L1; "d908" = 1 distance between parallel lines of L3 L5; "d909" = 10 distance from line of L2 A1.centre
extrude "押し出し82" cut sketch "スケッチ85" distance "d910" = 2; taper "d911" = 0 deg
sketch "スケッチ86"
  geometry: L1 (37, 38)-(37, 56.722) reference; L2 (60, 38)-(37, 38) reference; L3 (60, 56.722)-(60, 38) reference; L4 (42.5, 48)-(42.5, 42); L5 (42.5, 42)-(46.5, 42); L6 (46.5, 42)-(46.5, 48); L7 (50.5, 48)-(50.5, 42); L8 (50.5, 42)-(54.5, 42); L9 (54.5, 42)-(54.5, 48); A1 r 2 centre (44.5, 48) between (46.5, 48) and (42.5, 48); A2 r 2 centre (52.5, 48) between (54.5, 48) and (50.5, 48); 1 further point
  constraints: 12 end point, 4 parallel, 4 point on circle, 2 centre point, 2 perpendicular
  dimensions: "d912" = 4 distance between parallel lines of L7 L6; "d914" = 4 distance between parallel lines of L2 L5; "d915" = 5.5 distance between parallel lines of L1 L4; "d916" = 4 distance of L4.end L5.end; "d917" = 4 distance of L7.end L8.end; "d918" = 180 deg dimension on A1.centre L6.end L4.start; "d919" = 0 vertical distance of A2.centre A1.centre; "d920" = 0 vertical distance of L9.end L7.start; "d921" = 0 vertical distance of L7.start A2.centre; "d922" = 0 vertical distance of L4.start A1.centre; "d923" = 6 distance of L8.end L9.end; "d924" = 0 distance between parallel lines of L5 L8
extrude "押し出し83" cut sketch "スケッチ86" distance "d925" = 2; taper "d926" = 0 deg
sketch "スケッチ87"
  geometry: L1 (-7.5, 18.722)-(-7.5, 0) reference; L2 (0, 0)-(-7.5, 0) reference; L3 (0, 8)-(0, 0) reference; L4 (-6.5, 10)-(-6.5, 0); L5 (-1, 0)-(-1, 10); A1 r 2.75 centre (-3.75, 10) between (-1, 10) and (-6.5, 10); 1 further point
  constraints: 4 end point, 2 point on circle, 2 point on line, 2 tangent, 1 centre point, 1 parallel, 1 perpendicular
  dimensions: "d927" = 1 distance between parallel lines of L1 L4; "d928" = 1 distance between parallel lines of L3 L5; "d929" = 10 distance of L4.start L4.end
extrude "押し出し84" cut sketch "スケッチ87" distance "d930" = 2; taper "d931" = 0 deg
sketch "スケッチ88"
  geometry: L1 (0, -15.431)-(0, 0) reference; L2 (1, -15.431)-(0, -15.431) reference; L3 (1, -1.064)-(1, -15.431) reference; L4 (22, -1.064)-(1, -1.064) reference; L5 (22, -15.431)-(22, -1.064) reference; L6 (23, -15.431)-(22, -15.431) reference; L7 (23, 0)-(23, -15.431) reference; L8 (0, 0)-(23, 0) reference; L9 (-1, 3)-(24, 3); L10 (24, 3)-(24, -15.431); L11 (24, -15.431)-(-1, -15.431); L12 (-1, -15.431)-(-1, 3); 1 further point
  constraints: 8 end point, 2 parallel, 1 horizontal, 1 perpendicular
  dimensions: "d932" = 1 distance between parallel lines of L1 L12; "d933" = 1 distance between parallel lines of L10 L7; "d934" = 3 distance between parallel lines of L9 L8
extrude "roof00" join sketch "スケッチ88" distance "d935" = 1; taper "d936" = 0 deg
sketch "スケッチ89"
  geometry: L1 (22, 26)-(0, 26) reference; L2 (22, 0)-(22, 26) reference; L3 (20, 22)-(24, 22); L4 (24, 22)-(24, 34); L5 (24, 34)-(20, 34); L6 (20, 34)-(20, 22); 1 further point
  constraints: 8 end point, 2 parallel, 1 horizontal, 1 perpendicular
  dimensions: "d938" = 2 distance between parallel lines of L2 L6; "d939" = 4 distance of L4.end L5.end; "d940" = 4 distance between parallel lines of L3 L1; "d941" = 12 distance of L5.end L3.start
extrude "押し出し86" join sketch "スケッチ89" distance "d942" = 2; taper "d943" = 0 deg
sketch "スケッチ90"
  geometry: L1 (20, 34)-(24, 34); L2 (24, 34)-(24, 22); L3 (24, 22)-(20, 22); L4 (20, 22)-(20, 34); 1 further point
  constraints: 8 end point, 2 parallel, 1 horizontal, 1 perpendicular
  dimensions: "d1011" = 12 distance of L1.end L2.end (derived)
extrude "押し出し87" join sketch "スケッチ90" distance "d944" = 2; taper "d945" = 0 deg
sketch "スケッチ91"
  geometry: L1 (0, 4)-(4, 4) reference; L2 (0, 0)-(0, 4) reference; L3 (0, 0)-(4, 0) reference; L4 (4, 4)-(4, 0) reference; L5 (0, 4)-(4, 4); L6 (4, 4)-(4, 0); L7 (4, 0)-(0, 0); L8 (0, 0)-(0, 4); 1 further point
  constraints: 8 end point, 2 parallel, 1 horizontal, 1 perpendicular
  dimensions: "d946" = 0 distance between parallel lines of L2 L8; "d947" = 0 distance between parallel lines of L4 L6; "d948" = 0 distance between parallel lines of L1 L5; "d949" = 0 distance between parallel lines of L3 L7
extrude "押し出し88" join sketch "スケッチ91" distance "d950" = 1; taper "d951" = 0 deg
sketch "スケッチ92"
  geometry: L1 (4, 4)-(0, 4) reference; L2 (0, 4)-(0, 0) reference; L3 (0, 0)-(4, 0) reference; L4 (4, 0)-(4, 4) reference; L5 (0.5, 3.5)-(3.5, 3.5); L6 (3.5, 3.5)-(3.5, 0.5); L7 (3.5, 0.5)-(0.5, 0.5); L8 (0.5, 0.5)-(0.5, 3.5); 1 further point
  constraints: 8 end point, 2 parallel, 1 horizontal, 1 perpendicular
  dimensions: "d952" = 0.5 distance between parallel lines of L2 L8; "d953" = 0.5 distance between parallel lines of L4 L6; "d954" = 0.5 distance between parallel lines of L3 L7; "d955" = 0.5 distance between parallel lines of L1 L5
extrude "押し出し89" join sketch "スケッチ92" distance "d956" = 1; taper "d957" = 0 deg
